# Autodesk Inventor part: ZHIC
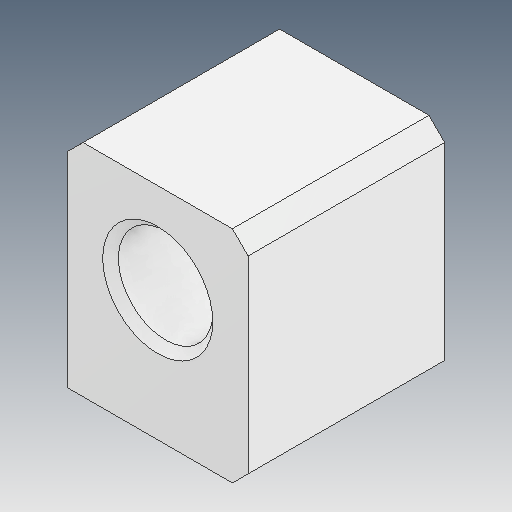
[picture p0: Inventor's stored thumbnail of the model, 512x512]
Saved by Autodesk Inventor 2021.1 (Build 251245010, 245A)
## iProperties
Created: 2021-05
Part Number: ZHIC
Material: Ogólny
Document SubType Name: Modeling
Designer: user
Density: 1 g/cm^3
Appearance: Domyślna
Author: user
Revision Number: ÈÎºÎ
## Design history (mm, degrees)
feature "ÊäÈë1"
node "Bryła1"
